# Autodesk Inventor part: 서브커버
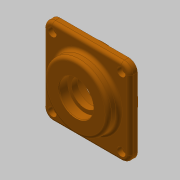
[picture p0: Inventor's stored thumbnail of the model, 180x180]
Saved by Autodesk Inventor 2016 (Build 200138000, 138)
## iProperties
Created: 2018-09
Part Number: 서브커버
Material: 알루미늄 6061
Document SubType Name: Modeling
Designer: mduedu
Density: 2.71 g/cm^3
Appearance: 주황색
Mass: 206.511 g
Surface Area: 197.007 cm^2
Volume: 76.2032 cm^3
Author: mduedu
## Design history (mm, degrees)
sketch "스케치1"
  geometry: L1 (-40, -40)-(40, -40); L2 (40, -40)-(40, 40); L3 (40, 40)-(-40, 40); L4 (-40, 40)-(-40, -40); L5 (-40, -40)-(40, 40); L6 (40, -40)-(-40, 40); 1 further point
  constraints: 12 end point, 2 midpoint, 2 parallel, 1 horizontal, 1 perpendicular
  dimensions: "d0" = 80 distance of L3.end L2.end; "d1" = 80 distance of L2.end L1.end
extrude "돌출1" new body sketch "스케치1" distance "d2" = 7; taper "d3" = 0 deg
sketch "스케치2"
  geometry: C1 r 30 at (0, 0); 1 further point
  constraints: 1 centre point, 1 coincident
  dimensions: "d4" = 60 diameter of C1
extrude "돌출2" join sketch "스케치2" distance "d5" = 10; taper "d6" = 0 deg
sketch "스케치3"
  geometry: C1 r 32.5 at (0, 0); 1 further point
  constraints: 1 centre point, 1 coincident
  dimensions: "d7" = 65 diameter of C1
extrude "돌출3" join sketch "스케치3" distance "d8" = 9; taper "d9" = 0 deg
sketch "스케치4"
  geometry: L1 (-32.5, -9)-(32.5, -9) reference; L2 (30, 17)-(-30, 17) reference; L3 (0, 17)-(0, -9); L4 (0, -9)-(20, -9); L5 (20, -9)-(20, 3); L6 (20, 3)-(0, 3); L7 (0, 3)-(0, -9); L8 (0, 3)-(12.5, 3); L9 (12.5, 3)-(12.5, 8.7); L10 (12.5, 8.7)-(0, 8.7); L11 (0, 8.7)-(0, 3); L12 (0, 8.7)-(16, 8.7); L13 (16, 8.7)-(16, 17); L14 (16, 17)-(0, 17); L15 (0, 17)-(0, 8.7); 1 further point
  constraints: 26 end point, 6 parallel, 3 horizontal, 3 perpendicular, 2 midpoint, 1 point on line
  dimensions: "d10" = 12 distance of L4.end L5.end; "d12" = 8.3 distance of L12.end L13.end; "d13" = 32 diameter of L13 L3; "d14" = 25 diameter of L9 L3; "d15" = 40 diameter of L5 L3
revolve "회전1" sketch "스케치4" stored, may be unused: angle "d16" = 90 deg
fillet "모깎기1" dims "d17" = 8
fillet "모깎기2" dims "d18" = 3
fillet "모깎기3" dims "d19" = 3
chamfer "모따기1" distance "d20" = 0.8; stored, may be unused: second distance "d21" = 2, angle "d22" = 30 deg
chamfer "모따기2" distance "d23" = 1; stored, may be unused: second distance "d24" = 2, angle "d25" = 30 deg
fillet "모깎기4" dims "d26" = 0.3
sketch "스케치5"
  geometry: A1 r 8 centre (-32, 32) between (-32, 40) and (-40, 32) reference; A2 r 8 centre (-32, -32) between (-40, -32) and (-32, -40) reference; A3 r 8 centre (32, -32) between (32, -40) and (40, -32) reference; A4 r 8 centre (32, 32) between (40, 32) and (32, 40) reference; 5 further points
  constraints: 4 coincident
hole "구멍1" sketch "스케치5" at (-32, 32), (32, 32), (32, -32), (-32, -32) diameter "d27" = 4.5; stored, may be unused: countersink angle "d31" = 90 deg, drill point angle "d33" = 118 deg; dims "d28" = 6, "d29" = 8, "d30" = 4.4, "d32" = 8
node "솔리드1"
